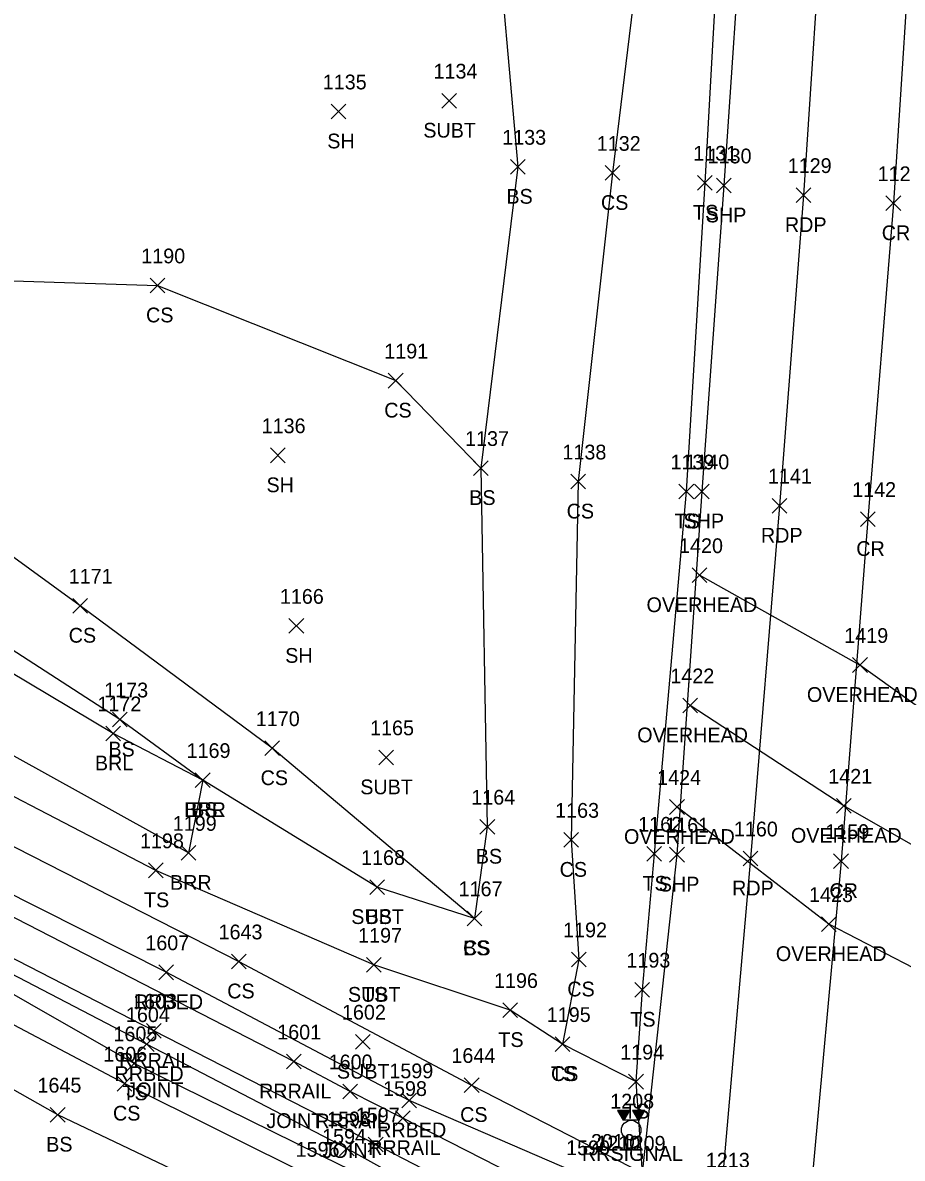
# Model space of a CAD drawing. Extents: x 1443960 to 1446865, y 610387 to 616706.
# Drawn here: x 1446493.6 to 1446612.8, y 611170.6 to 611324.5 of the extents above; entities that cross this region are included whole.
import ezdxf

# ---------------------------------------------------------------- set-up
doc = ezdxf.new("R2010")
doc.units = 0
for name, color, linetype in [('L_A', 7, 'Continuous'), ('L_I', 7, 'Continuous'), ('L_TIC', 7, 'Continuous'), ('LABL', 7, 'Continuous'), ('LELB', 7, 'Continuous'), ('P_A', 7, 'Continuous'), ('P_I', 7, 'Continuous'), ('P_TIC', 7, 'Continuous'), ('PET', 7, 'Continuous'), ('PRC', 7, 'Continuous'), ('PSP', 7, 'Continuous'), ('R_A', 7, 'Continuous'), ('R_C', 7, 'Continuous'), ('R_I', 7, 'Continuous'), ('R_TIC', 7, 'Continuous'), ('RR', 7, 'Continuous'), ('RRB', 7, 'Continuous'), ('TCSH', 7, 'Continuous'), ('U_A', 7, 'Continuous'), ('U_I', 7, 'Continuous'), ('U_TIC', 7, 'Continuous'), ('UCO', 7, 'Continuous')]:
    doc.layers.add(name, color=color, linetype=linetype)

msp = doc.modelspace()

# ---------------------------------------------------------------- linework, layer by layer
at = {"layer": 'L_TIC'}
for points in [[(1446535.36, 611311.49), (1446537.36, 611313.49)], [(1446537.36, 611311.49), (1446535.36, 611313.49)], [(1446559.67, 611303.99), (1446561.67, 611305.99)], [(1446561.67, 611303.99), (1446559.67, 611305.99)], [(1446572.49, 611303.16), (1446574.49, 611305.16)], [(1446574.49, 611303.16), (1446572.49, 611305.16)], [(1446584.99, 611301.83), (1446586.99, 611303.83)], [(1446586.99, 611301.83), (1446584.99, 611303.83)], [(1446510.86, 611287.91), (1446512.86, 611289.91)], [(1446512.86, 611287.91), (1446510.86, 611289.91)], [(1446543.12, 611275.01), (1446545.12, 611277.01)], [(1446545.12, 611275.01), (1446543.12, 611277.01)], [(1446527.14, 611264.89), (1446529.14, 611266.89)], [(1446529.14, 611264.89), (1446527.14, 611266.89)], [(1446554.64, 611263.16), (1446556.64, 611265.16)], [(1446556.64, 611263.16), (1446554.64, 611265.16)], [(1446567.84, 611261.33), (1446569.84, 611263.33)], [(1446569.84, 611261.33), (1446567.84, 611263.33)], [(1446582.49, 611259.98), (1446584.49, 611261.98)], [(1446584.49, 611259.98), (1446582.49, 611261.98)], [(1446500.38, 611244.5), (1446502.38, 611246.5)], [(1446502.38, 611244.5), (1446500.38, 611246.5)], [(1446529.66, 611241.77), (1446531.66, 611243.77)], [(1446531.66, 611241.77), (1446529.66, 611243.77)], [(1446505.75, 611229.08), (1446507.75, 611231.08)], [(1446507.75, 611229.08), (1446505.75, 611231.08)], [(1446504.83, 611227.19), (1446506.83, 611229.19)], [(1446506.83, 611227.19), (1446504.83, 611229.19)], [(1446526.38, 611225.19), (1446528.38, 611227.19)], [(1446528.38, 611225.19), (1446526.38, 611227.19)], [(1446516.97, 611220.87), (1446518.97, 611222.87)], [(1446518.97, 611220.87), (1446516.97, 611222.87)], [(1446516.97, 611220.87), (1446518.97, 611222.87)], [(1446518.97, 611220.87), (1446516.97, 611222.87)], [(1446516.97, 611220.87), (1446518.97, 611222.87)], [(1446518.97, 611220.87), (1446516.97, 611222.87)], [(1446555.53, 611214.55), (1446557.53, 611216.55)], [(1446557.53, 611214.55), (1446555.53, 611216.55)], [(1446566.89, 611212.77), (1446568.89, 611214.77)], [(1446568.89, 611212.77), (1446566.89, 611214.77)], [(1446515.05, 611211), (1446517.05, 611213)], [(1446517.05, 611211), (1446515.05, 611213)], [(1446578.14, 611210.88), (1446580.14, 611212.88)], [(1446580.14, 611210.88), (1446578.14, 611212.88)], [(1446510.61, 611208.64), (1446512.61, 611210.64)], [(1446512.61, 611208.64), (1446510.61, 611210.64)], [(1446540.6, 611206.37), (1446542.6, 611208.37)], [(1446542.6, 611206.37), (1446540.6, 611208.37)], [(1446553.81, 611202.13), (1446555.81, 611204.13)], [(1446555.81, 611202.13), (1446553.81, 611204.13)], [(1446553.81, 611202.13), (1446555.81, 611204.13)], [(1446555.81, 611202.13), (1446553.81, 611204.13)], [(1446521.86, 611196.29), (1446523.86, 611198.29)], [(1446523.86, 611196.29), (1446521.86, 611198.29)], [(1446540.15, 611195.83), (1446542.15, 611197.83)], [(1446542.15, 611195.83), (1446540.15, 611197.83)], [(1446567.92, 611196.56), (1446569.92, 611198.56)], [(1446569.92, 611196.56), (1446567.92, 611198.56)], [(1446576.5, 611192.46), (1446578.5, 611194.46)], [(1446578.5, 611192.46), (1446576.5, 611194.46)], [(1446558.62, 611189.7), (1446560.62, 611191.7)], [(1446560.62, 611189.7), (1446558.62, 611191.7)], [(1446565.72, 611185.09), (1446567.72, 611187.09)], [(1446567.72, 611185.09), (1446565.72, 611187.09)], [(1446565.72, 611185.09), (1446567.72, 611187.09)], [(1446567.72, 611185.09), (1446565.72, 611187.09)], [(1446507.69, 611182.48), (1446509.69, 611184.48)], [(1446509.69, 611182.48), (1446507.69, 611184.48)], [(1446575.67, 611180), (1446577.67, 611182)], [(1446577.67, 611180), (1446575.67, 611182)], [(1446575.67, 611180), (1446577.67, 611182)], [(1446577.67, 611180), (1446575.67, 611182)], [(1446506.38, 611179.73), (1446508.38, 611181.73)], [(1446508.38, 611179.73), (1446506.38, 611181.73)], [(1446553.41, 611179.54), (1446555.41, 611181.54)], [(1446555.41, 611179.54), (1446553.41, 611181.54)], [(1446497.33, 611175.52), (1446499.33, 611177.52)], [(1446499.33, 611175.52), (1446497.33, 611177.52)]]:
    msp.add_lwpolyline(points, dxfattribs=at)
at = {"layer": 'LABL'}
for points in [[(1446517.97, 611221.87), (1446505.83, 611228.19), (1446480.13, 611243.51), (1446438.08, 611264.66), (1446410.71, 611279.39), (1446397.71, 611287.62), (1446399.45, 611289.73), (1446412.36, 611290.47), (1446420.56, 611296.87), (1446396.67, 611304.52)], [(1446517.97, 611221.87), (1446516.05, 611212), (1446478.3, 611232.93), (1446443.39, 611246.75), (1446407.2, 611268.28), (1446380.98, 611283.12)]]:
    msp.add_lwpolyline(points, dxfattribs=at)
at = {"layer": 'LELB'}
for points in [[(1446577.92, 611397.13), (1446574.23, 611374.21), (1446578.3, 611343.49), (1446573.49, 611304.16), (1446568.84, 611262.33), (1446567.89, 611213.77), (1446568.92, 611197.56), (1446566.72, 611186.09)], [(1446591.91, 611396.62), (1446591.29, 611373.02), (1446588.27, 611343.45), (1446585.99, 611302.83), (1446583.49, 611260.98), (1446579.14, 611211.88), (1446577.5, 611193.46), (1446576.67, 611181), (1446577.51, 611168.64)], [(1446552.99, 611382.07), (1446558.67, 611362.69), (1446557.44, 611341.16), (1446560.67, 611304.99), (1446555.64, 611264.16), (1446556.53, 611215.55), (1446554.81, 611203.13), (1446541.6, 611207.37), (1446517.97, 611221.87), (1446506.75, 611230.08), (1446482.61, 611245.67), (1446443.05, 611268.8), (1446411.93, 611283.54), (1446399.45, 611289.73)], [(1446420.56, 611296.87), (1446442.81, 611293.9), (1446482.45, 611289.85), (1446511.86, 611288.91), (1446544.12, 611276.01)], [(1446554.81, 611203.13), (1446527.38, 611226.19), (1446501.38, 611245.5), (1446484.03, 611258.08), (1446449.7, 611278.6), (1446412.36, 611290.47)], [(1446344.24, 611288.47), (1446379.4, 611269.73), (1446415.39, 611251.12), (1446451.44, 611233.03), (1446488.32, 611214.89), (1446522.86, 611197.29), (1446554.41, 611180.54)], [(1446576.67, 611181), (1446566.72, 611186.09), (1446559.62, 611190.7), (1446541.15, 611196.83), (1446511.61, 611209.64), (1446476.68, 611227.8), (1446439.45, 611243.81), (1446404.54, 611264.4), (1446379.18, 611279.89)], [(1446555.64, 611264.16), (1446544.12, 611276.01)], [(1446548.85, 610888.19), (1446553.44, 610932.22), (1446554.61, 610954.43), (1446557.18, 610985.54), (1446561.83, 611026.07), (1446565.58, 611053.66), (1446570.69, 611096.92), (1446573.29, 611130.79), (1446568.51, 611145), (1446569.91, 611148.66), (1446564.88, 611156.7), (1446536.84, 611169.59), (1446508.69, 611183.48), (1446466.55, 611207.56), (1446427.27, 611227.8), (1446388.8, 611245), (1446349.69, 611268.25), (1446343.09, 611268.96)], [(1446552.43, 611156.81), (1446533.31, 611167.82), (1446507.38, 611180.73), (1446464.69, 611203.31), (1446425.68, 611223.52), (1446387.19, 611242.09), (1446349.13, 611263.69), (1446342.52, 611266.22)], [(1446545.33, 610990.77), (1446549.45, 611028.52), (1446549.03, 611055.59), (1446553.29, 611104.25), (1446542.01, 611115.66), (1446540.05, 611127.24), (1446544.04, 611129.96), (1446551.51, 611136.49), (1446553.27, 611138.91), (1446550.53, 611149.51), (1446533.12, 611159.93), (1446498.33, 611176.52), (1446468.4, 611193.46), (1446432.91, 611211.11), (1446396.49, 611230.29), (1446366.67, 611244.64), (1446348.43, 611256.48)], [(1446554.41, 611180.54), (1446577.51, 611168.64)]]:
    msp.add_lwpolyline(points, dxfattribs=at)
at = {"layer": 'P_TIC'}
for points in [[(1446587.59, 611301.46), (1446589.59, 611303.46)], [(1446589.59, 611301.46), (1446587.59, 611303.46)], [(1446598.36, 611300.15), (1446600.36, 611302.15)], [(1446600.36, 611300.15), (1446598.36, 611302.15)], [(1446610.54, 611299.05), (1446612.54, 611301.05)], [(1446612.54, 611299.05), (1446610.54, 611301.05)], [(1446584.58, 611260), (1446586.58, 611262)], [(1446586.58, 611260), (1446584.58, 611262)], [(1446595.11, 611258.06), (1446597.11, 611260.06)], [(1446597.11, 611258.06), (1446595.11, 611260.06)], [(1446607.09, 611256.25), (1446609.09, 611258.25)], [(1446609.09, 611256.25), (1446607.09, 611258.25)], [(1446581.23, 611210.77), (1446583.23, 611212.77)], [(1446583.23, 611210.77), (1446581.23, 611212.77)], [(1446591.2, 611210.24), (1446593.2, 611212.24)], [(1446593.2, 611210.24), (1446591.2, 611212.24)], [(1446603.45, 611209.89), (1446605.45, 611211.89)], [(1446605.45, 611209.89), (1446603.45, 611211.89)]]:
    msp.add_lwpolyline(points, dxfattribs=at)
at = {"layer": 'PET'}
msp.add_lwpolyline([(1446607.25, 611453.94), (1446606.67, 611433.53), (1446604.98, 611393.16), (1446602.22, 611344.38), (1446599.36, 611301.15), (1446596.11, 611259.06), (1446592.2, 611211.24), (1446588.27, 611166.36), (1446587.47, 611154.32)], dxfattribs=at)
at = {"layer": 'PRC'}
msp.add_lwpolyline([(1446619.86, 611450.5), (1446619.25, 611432.43), (1446617.28, 611389.69), (1446614.4, 611344.28), (1446611.54, 611300.05), (1446608.09, 611257.25), (1446604.45, 611210.89), (1446600.19, 611163.97), (1446598.97, 611148.35)], dxfattribs=at)
at = {"layer": 'PSP'}
msp.add_lwpolyline([(1446591.31, 611343.17), (1446588.59, 611302.46), (1446585.58, 611261), (1446582.23, 611211.77), (1446577.51, 611168.64), (1446576.96, 611160.22), (1446577.27, 611159.61)], dxfattribs=at)
at = {"layer": 'R_TIC'}
for points in [[(1446512.02, 611194.82), (1446514.02, 611196.82)], [(1446514.02, 611194.82), (1446512.02, 611196.82)], [(1446510.36, 611186.89), (1446512.36, 611188.89)], [(1446512.36, 611186.89), (1446510.36, 611188.89)], [(1446509.38, 611185.08), (1446511.38, 611187.08)], [(1446511.38, 611185.08), (1446509.38, 611187.08)], [(1446529.32, 611182.72), (1446531.32, 611184.72)], [(1446531.32, 611182.72), (1446529.32, 611184.72)], [(1446536.95, 611178.67), (1446538.95, 611180.67)], [(1446538.95, 611178.67), (1446536.95, 611180.67)], [(1446544.96, 611177.46), (1446546.96, 611179.46)], [(1446546.96, 611177.46), (1446544.96, 611179.46)], [(1446544.1, 611175.06), (1446546.1, 611177.06)], [(1446546.1, 611175.06), (1446544.1, 611177.06)], [(1446536.51, 611170.94), (1446538.51, 611172.94)], [(1446538.51, 611170.94), (1446536.51, 611172.94)], [(1446540.41, 611171.48), (1446542.41, 611173.48)], [(1446542.41, 611171.48), (1446540.41, 611173.48)]]:
    msp.add_lwpolyline(points, dxfattribs=at)
at = {"layer": 'RR'}
for points in [[(1446830.8, 611028.51), (1446813.8, 611037.34), (1446780.13, 611054.63), (1446766.6, 611061.72), (1446723.16, 611084.18), (1446681.83, 611105.5), (1446667.65, 611112.72), (1446650.45, 611121.75), (1446635.82, 611129.05), (1446620.36, 611137.27), (1446611.04, 611142.08), (1446598.97, 611148.35), (1446587.47, 611154.32), (1446577.27, 611159.61), (1446545.1, 611176.06), (1446537.95, 611179.67), (1446530.32, 611183.72), (1446472.23, 611213.59), (1446430.68, 611235.02), (1446393.22, 611254.19), (1446353.39, 611274.79), (1446345.67, 611278.8)], [(1446830.61, 611022.91), (1446812, 611032.72), (1446777.67, 611050.48), (1446764.9, 611057.05), (1446720.8, 611079.76), (1446679.61, 611101.04), (1446672.6, 611104.75), (1446648.09, 611117.4), (1446634.05, 611124.73), (1446619.04, 611132.42), (1446610.71, 611136.75), (1446598.39, 611142.94), (1446586.96, 611148.93), (1446576.92, 611154.08), (1446541.41, 611172.48), (1446511.36, 611187.89), (1446469.88, 611209.21), (1446428.54, 611230.42), (1446391.04, 611249.76), (1446351.07, 611270.34), (1446343.04, 611274.54)]]:
    msp.add_lwpolyline(points, dxfattribs=at)
at = {"layer": 'RRB'}
for points in [[(1446569.99, 611168.04), (1446545.96, 611178.46), (1446513.02, 611195.82), (1446473.29, 611215.85), (1446431.72, 611237.21), (1446394.07, 611256.06), (1446354.34, 611276.82), (1446346.71, 611281.18)], [(1446564.88, 611156.7), (1446537.51, 611171.94), (1446510.38, 611186.08), (1446466.95, 611208.66), (1446427.98, 611228.69), (1446390.24, 611247.7), (1446350.09, 611268.94), (1446342.68, 611272.23)]]:
    msp.add_lwpolyline(points, dxfattribs=at)
at = {"layer": 'TCSH'}
for p, q in [((1446575.84, 611177.1), (1446574.17, 611177.1)), ((1446574.17, 611177.1), (1446574.94, 611175.77)), ((1446575.07, 611175.77), (1446575.84, 611177.1)), ((1446577.87, 611177.1), (1446576.21, 611177.1)), ((1446576.21, 611177.1), (1446576.98, 611175.77)), ((1446577.1, 611175.77), (1446577.87, 611177.1)), ((1446577.1, 611175.77), (1446574.94, 611175.77)), ((1446576.02, 611174.43), (1446576.02, 611174.43))]:
    msp.add_line(p, q, dxfattribs=at)
for points in [[(1446574.22, 611177.02), (1446575.8, 611177.02)], [(1446574.29, 611176.89), (1446575.72, 611176.89)], [(1446574.37, 611176.76), (1446575.64, 611176.76)], [(1446574.45, 611176.62), (1446575.56, 611176.62)], [(1446574.52, 611176.49), (1446575.49, 611176.49)], [(1446574.6, 611176.36), (1446575.41, 611176.36)], [(1446574.68, 611176.22), (1446575.33, 611176.22)], [(1446574.76, 611176.09), (1446575.26, 611176.09)], [(1446574.83, 611175.96), (1446575.18, 611175.96)], [(1446574.91, 611175.82), (1446575.1, 611175.82)], [(1446576.24, 611177.05), (1446577.85, 611177.05)], [(1446576.31, 611176.92), (1446577.77, 611176.92)], [(1446576.39, 611176.79), (1446577.69, 611176.79)], [(1446576.47, 611176.65), (1446577.62, 611176.65)], [(1446576.54, 611176.52), (1446577.54, 611176.52)], [(1446576.62, 611176.39), (1446577.46, 611176.39)], [(1446576.7, 611176.25), (1446577.38, 611176.25)], [(1446576.77, 611176.12), (1446577.31, 611176.12)], [(1446576.85, 611175.99), (1446577.23, 611175.99)], [(1446576.93, 611175.85), (1446577.15, 611175.85)]]:
    msp.add_lwpolyline(points, dxfattribs=at)
msp.add_circle((1446576.02, 611174.43), 1.33, dxfattribs=at)
at = {"layer": 'U_TIC'}
for points in [[(1446550.36, 611312.95), (1446552.36, 611314.95)], [(1446552.36, 611312.95), (1446550.36, 611314.95)], [(1446584.29, 611248.64), (1446586.29, 611250.64)], [(1446586.29, 611248.64), (1446584.29, 611250.64)], [(1446606.02, 611236.47), (1446608.02, 611238.47)], [(1446608.02, 611236.47), (1446606.02, 611238.47)], [(1446583.03, 611230.99), (1446585.03, 611232.99)], [(1446585.03, 611230.99), (1446583.03, 611232.99)], [(1446541.82, 611223.95), (1446543.82, 611225.95)], [(1446543.82, 611223.95), (1446541.82, 611225.95)], [(1446581.23, 611217.23), (1446583.23, 611219.23)], [(1446583.23, 611217.23), (1446581.23, 611219.23)], [(1446603.84, 611217.38), (1446605.84, 611219.38)], [(1446605.84, 611217.38), (1446603.84, 611219.38)], [(1446540.6, 611206.37), (1446542.6, 611208.37)], [(1446542.6, 611206.37), (1446540.6, 611208.37)], [(1446601.81, 611201.35), (1446603.81, 611203.35)], [(1446603.81, 611201.35), (1446601.81, 611203.35)], [(1446540.15, 611195.83), (1446542.15, 611197.83)], [(1446542.15, 611195.83), (1446540.15, 611197.83)], [(1446538.66, 611185.41), (1446540.66, 611187.41)], [(1446540.66, 611185.41), (1446538.66, 611187.41)]]:
    msp.add_lwpolyline(points, dxfattribs=at)
at = {"layer": 'UCO'}
for points in [[(1446628.23, 611222.21), (1446607.02, 611237.47), (1446585.29, 611249.64)], [(1446626.79, 611205.81), (1446604.84, 611218.38), (1446584.03, 611231.99)], [(1446625.83, 611190.44), (1446602.81, 611202.35), (1446582.23, 611218.23)]]:
    msp.add_lwpolyline(points, dxfattribs=at)

# ---------------------------------------------------------------- texts
at = {"layer": 'L_A'}
for s, p in [('SH', (1446534.85, 611307.49)), ('BS', (1446559.12, 611299.99)), ('CS', (1446571.93, 611299.16)), ('TS', (1446584.4, 611297.83)), ('CS', (1446510.3, 611283.91)), ('CS', (1446542.57, 611271.01)), ('SH', (1446526.62, 611260.89)), ('BS', (1446554.08, 611259.16)), ('CS', (1446567.28, 611257.33)), ('TS', (1446581.9, 611255.98)), ('CS', (1446499.82, 611240.5)), ('SH', (1446529.15, 611237.77)), ('BS', (1446505.2, 611225.08)), ('BRL', (1446503.37, 611223.19)), ('CS', (1446525.82, 611221.19)), ('BS', (1446516.41, 611216.87)), ('BRR', (1446515.46, 611216.87)), ('BRL', (1446515.51, 611216.87)), ('BS', (1446554.97, 611210.55)), ('CS', (1446566.33, 611208.77)), ('BRR', (1446513.54, 611207)), ('TS', (1446577.55, 611206.88)), ('TS', (1446510.02, 611204.64)), ('BS', (1446540.04, 611202.37)), ('CS', (1446553.25, 611198.13)), ('BS', (1446553.25, 611198.13)), ('CS', (1446521.3, 611192.29)), ('CS', (1446567.37, 611192.56)), ('TS', (1446539.56, 611191.83)), ('TS', (1446575.91, 611188.46)), ('TS', (1446558.03, 611185.7)), ('TS', (1446565.13, 611181.09)), ('CS', (1446565.16, 611181.09)), ('TS', (1446507.1, 611178.48)), ('CS', (1446505.82, 611175.73)), ('CS', (1446552.85, 611175.54)), ('TS', (1446575.07, 611176)), ('TS', (1446575.07, 611176)), ('BS', (1446496.77, 611171.52))]:
    msp.add_text(s, height=2, dxfattribs=at).set_placement(p)
at = {"layer": 'L_I'}
for s, p in [('1135', (1446534.24, 611315.49)), ('1133', (1446558.55, 611307.99)), ('1132', (1446571.36, 611307.16)), ('1131', (1446584.43, 611305.83)), ('1190', (1446509.65, 611291.91)), ('1191', (1446542.57, 611279.01)), ('1136', (1446525.96, 611268.89)), ('1137', (1446553.52, 611267.16)), ('1138', (1446566.71, 611265.33)), ('1139', (1446581.35, 611263.98)), ('1171', (1446499.82, 611248.5)), ('1166', (1446528.43, 611245.77)), ('1173', (1446504.63, 611233.08)), ('1172', (1446503.71, 611231.19)), ('1170', (1446525.17, 611229.19)), ('1169', (1446515.79, 611224.87)), ('1169', (1446515.79, 611224.87)), ('1169', (1446515.79, 611224.87)), ('1164', (1446554.36, 611218.55)), ('1163', (1446565.72, 611216.77)), ('1199', (1446513.92, 611215)), ('1162', (1446576.97, 611214.88)), ('1198', (1446509.48, 611212.64)), ('1168', (1446539.43, 611210.37)), ('1167', (1446552.64, 611206.13)), ('1167', (1446552.64, 611206.13)), ('1643', (1446520.12, 611200.29)), ('1192', (1446566.8, 611200.56)), ('1197', (1446539.03, 611199.83)), ('1193', (1446575.38, 611196.46)), ('1196', (1446557.44, 611193.7)), ('1195', (1446564.59, 611189.09)), ('1195', (1446564.59, 611189.09)), ('1605', (1446505.88, 611186.48)), ('1606', (1446504.51, 611183.73)), ('1644', (1446551.67, 611183.54)), ('1194', (1446574.54, 611184)), ('1194', (1446574.54, 611184)), ('1645', (1446495.59, 611179.52)), ('1594', (1446534.15, 611172.59)), ('1596', (1446530.56, 611170.82)), ('2010', (1446570.57, 611171.9)), ('1209', (1446574.73, 611171.64))]:
    msp.add_text(s, height=2, dxfattribs=at).set_placement(p)
at = {"layer": 'P_A'}
for s, p in [('SHP', (1446586.13, 611297.46)), ('RDP', (1446596.85, 611296.15)), ('CR', (1446609.97, 611295.05)), ('SHP', (1446583.11, 611256)), ('RDP', (1446593.6, 611254.06)), ('CR', (1446606.52, 611252.25)), ('SHP', (1446579.77, 611206.77)), ('RDP', (1446589.69, 611206.24)), ('CR', (1446602.88, 611205.89))]:
    msp.add_text(s, height=2, dxfattribs=at).set_placement(p)
at = {"layer": 'P_I'}
for s, p in [('1130', (1446586.38, 611305.46)), ('1129', (1446597.23, 611304.15)), ('1128', (1446609.41, 611303.05)), ('1140', (1446583.36, 611264)), ('1141', (1446594.55, 611262.06)), ('1142', (1446605.96, 611260.25)), ('1161', (1446580.63, 611214.77)), ('1160', (1446589.94, 611214.24)), ('1159', (1446602.32, 611213.89)), ('1209', (1446574.73, 611171.64)), ('1213', (1446586.14, 611169.36))]:
    msp.add_text(s, height=2, dxfattribs=at).set_placement(p)
at = {"layer": 'R_A'}
for s, p in [('RRBED', (1446508.66, 611190.82)), ('RRRAIL', (1446506.65, 611182.89)), ('RRBED', (1446506.03, 611181.08)), ('RRRAIL', (1446525.61, 611178.72)), ('RRRAIL', (1446533.24, 611174.67)), ('RRBED', (1446541.61, 611173.46)), ('RRRAIL', (1446540.39, 611171.06)), ('RRSIGNAL', (1446569.35, 611170.26))]:
    msp.add_text(s, height=2, dxfattribs=at).set_placement(p)
at = {"layer": 'R_C'}
for p in [(1446507.64, 611178.89), (1446526.6, 611174.72), (1446534.22, 611170.67)]:
    msp.add_text('JOINT', height=2, dxfattribs=at).set_placement(p)
at = {"layer": 'R_I'}
for s, p in [('1607', (1446510.2, 611198.82)), ('1603', (1446508.54, 611190.89)), ('1604', (1446507.57, 611189.08)), ('1601', (1446528.07, 611186.72)), ('1600', (1446535.04, 611182.67)), ('1599', (1446543.26, 611181.46)), ('1598', (1446542.4, 611179.06)), ('1208', (1446573.18, 611177.36)), ('1597', (1446538.72, 611175.48)), ('1593', (1446534.82, 611174.94)), ('1590', (1446567.21, 611171.04)), ('1210', (1446571.29, 611171.66)), ('1209', (1446574.73, 611171.64))]:
    msp.add_text(s, height=2, dxfattribs=at).set_placement(p)
at = {"layer": 'U_A'}
for s, p in [('SUBT', (1446547.86, 611308.95)), ('OVERHEAD', (1446578.1, 611244.64)), ('OVERHEAD', (1446599.83, 611232.47)), ('OVERHEAD', (1446576.84, 611226.99)), ('SUBT', (1446539.32, 611219.95)), ('OVERHEAD', (1446575.05, 611213.23)), ('OVERHEAD', (1446597.66, 611213.38)), ('SUBT', (1446538.1, 611202.37)), ('OVERHEAD', (1446595.62, 611197.35)), ('SUBT', (1446537.65, 611191.83)), ('SUBT', (1446536.16, 611181.41))]:
    msp.add_text(s, height=2, dxfattribs=at).set_placement(p)
at = {"layer": 'U_I'}
for s, p in [('1134', (1446549.24, 611316.95)), ('1420', (1446582.51, 611252.64)), ('1419', (1446604.89, 611240.47)), ('1422', (1446581.33, 611234.99)), ('1165', (1446540.65, 611227.95)), ('1424', (1446579.54, 611221.23)), ('1421', (1446602.72, 611221.38)), ('1168', (1446539.43, 611210.37)), ('1423', (1446600.12, 611205.35)), ('1197', (1446539.03, 611199.83)), ('1602', (1446536.84, 611189.41)), ('1594', (1446534.15, 611172.59))]:
    msp.add_text(s, height=2, dxfattribs=at).set_placement(p)

doc.saveas('drawing.dxf')
